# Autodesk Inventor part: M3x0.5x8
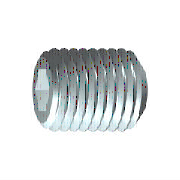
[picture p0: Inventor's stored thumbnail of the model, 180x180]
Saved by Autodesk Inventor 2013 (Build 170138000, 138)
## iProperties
IsCustomPart: 1
Company: 한국ATC센터
Created: 2009-02
Part Number: M3x0.5x8
Material: 강, 연강
Description: 6각 소켓 머리 없는 멈춤 나사
Document SubType Name: Modeling
Standard: KS B 1028
Designer: KYOUNG IL JANG
Standards Organization: KS
Language: ko-KR
Size Designation: 납작점M3x6
Categories: <MemberInstance><Categories><Category DisplayName="조임쇠" InternalName="e4da775c-781d-43d5-af7c-5136215cf5a6" Mnemonic="FSTN"><Category DisplayName="볼트" InternalN
Density: 7.86 g/cm^3
Mass: 0.293227 g
Surface Area: 0.779768 cm^2
Volume: 0.0373062 cm^3
Vendor: CBT Solutions
Author: KYOUNG IL JANG
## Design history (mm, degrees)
sketch "스케치1"
  geometry: L1 (0, 0)-(3.5, 0); L2 (6, 0.866)-(6, 1.5); L3 (6, 1.5)-(0, 1.5); L4 (6, 0.866)-(4, 0.866); L5 (4, 0.866)-(3.5, 0); L6 (0, -0.3)-(0, 1.8) reference; L7 (0, 1.5)-(0, 0)
  constraints: 13 end point, 3 parallel, 1 collinear, 1 perpendicular, 1 point on line
  dimensions: "d0" = 2 distance of L2.start L4.end (= INTI); "d1" = 60 deg angle of L5 L1; "d2" = 3 diameter of L3 L1 (= NND); "d3" = 1.73205 diameter of L4 L1 (= 1.1547 x SW); "d5" = 6 distance from line of L2 L3.end (= NLG)
revolve "본체" sketch "스케치1" stored, may be unused: angle "d6" = 90 deg
sketch "스케치2"
  geometry: L1 (-0.433, 0.75)-(0.433, 0.75); L2 (0.433, 0.75)-(0.866, 0); L3 (0.866, 0)-(0.433, -0.75); L4 (0.433, -0.75)-(-0.433, -0.75); L5 (-0.433, -0.75)-(-0.866, 0); L6 (-0.866, 0)-(-0.433, 0.75); A1 r 0.866 centre (0, 0) between (-0.433, 0.75) and (0.433, 0.75) reference; 2 further points
  constraints: 12 end point, 2 point on circle, 1 coincident, 1 horizontal, 11 other
extrude "슬롯" join sketch "스케치2" taper "d9" = 0 deg; stored distance "d21" = 10
workaxis "Work Axis1"
workplane "Work Plane1"
body "Solid1"
chamfer "모따기1" distance "d7" = 0.30673 (= -0.5 x GD1 + 0.5 x NND); stored, may be unused: angle "d8" = 45 deg (= FAWI), second distance "d29" = 0.30673 (= -0.5 x GD1 + 0.5 x NND)
feature "스레드" dims "d11" = 6 (= NLG), "d12" = 0
chamfer "모따기2" distance "d13" = 0.30673 (= -0.5 x GD1 + 0.5 x NND); stored, may be unused: angle "d14" = 45 deg (= FAWI), second distance "d30" = 0.30673 (= -0.5 x GD1 + 0.5 x NND)
other parameters: "NND" = 3 [user parameter; used in 5 equation terms], "NLG" = 6 [user parameter; used in 2 equation terms], "INTI" = 2 [user parameter; used in 1 equation term], "FAWI" = 45 deg [user parameter; used in 2 equation terms], "SW" = 1.5 [user parameter; used in 2 equation terms], "GD1" = 2.38655 (= THREADDIA - 1.2269 x PTC) [user parameter; used in 4 equation terms], "d4" = 0, "FAWI1" = 45 deg [user parameter], "d15" = 0, "d31" = 0, "GUL" = 0.30673 (= 0.61345 x PTC) [user parameter], "SPD" = 2 [user parameter], "TOA" = 30 deg [user parameter], "THREADDIA" = 3 [user parameter; used in 1 equation term], "PTC" = 0.5 [user parameter; used in 4 equation terms], "GAL" = 0.30673 (= 0.61345 x PTC) [user parameter], "E0" = 1.7325 (= 1.155 x SW) [user parameter]
